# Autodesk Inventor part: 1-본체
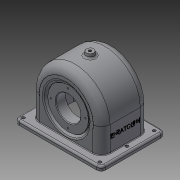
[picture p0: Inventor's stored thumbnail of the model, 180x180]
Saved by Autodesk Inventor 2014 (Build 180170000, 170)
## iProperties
Created: 2015-09
Part Number: 1-본체
Material: 일반
Document SubType Name: Modeling
Designer: Administrator
Density: 1 g/cm^3
Appearance: 기본값
Author: Administrator
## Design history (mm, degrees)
sketch "스케치1"
  geometry: L1 (57, 0)-(-57, 0); L2 (-57, 0)-(-57, -40); L3 (-57, -40)-(57, -40); L4 (57, -40)-(57, 0); L5 (70, -40)-(-70, -40); L6 (-70, -40)-(-70, -47); L7 (-70, -47)-(70, -47); L8 (70, -47)-(70, -40); A1 r 57 centre (0, 0) between (57, 0) and (40.608, -40); 6 further points
  constraints: 16 end point, 5 point on circle, 4 parallel, 4 point on line, 3 midpoint, 2 coincident, 2 horizontal, 2 perpendicular, 1 centre point
  dimensions: "d0" = 114 diameter of A1; "d1" = 7 distance of L5.end L6.end; "d2" = 47 distance between parallel lines of L1 L7; "d3" = 140 distance of L6.end L7.end
extrude "돌출1" new body sketch "스케치1" stored distance "d4" = 77; taper "d5" = 0 deg
extrude "돌출2" join sketch "스케치1" stored distance "d6" = 104; taper "d7" = 0 deg
fillet "모깎기1" dims "d12" = 14
feature "쉘1" dims "d13" = 7, "d14" = 5
sketch "스케치2"
  geometry: L1 (-38.5, 43.943)-(-38.5, 0); L2 (-38.5, 0)-(-19.5, 0); L3 (-19.5, 0)-(-19.5, 28); L4 (-19.5, 28)-(-38.5, 43.943); L5 (-38.5, 0)-(-38.5, 43) reference; L6 (24.5, 0)-(-24.5, 0) reference; L7 (-33.5, 33.22)-(-33.5, 5); L8 (-33.5, 5)-(-24.5, 5); L9 (-24.5, 5)-(-24.5, 25.668); L10 (-24.5, 25.668)-(-33.5, 33.22); L11 (-38.5, 37.416)-(-19.5, 21.473); 1 further point
  constraints: 18 end point, 3 point on line, 2 collinear, 2 parallel, 2 perpendicular, 1 midpoint, 1 vertical, 3 other
  dimensions: "d24" = 19 distance between parallel lines of L1 L3; "d25" = 50 deg angle of L3 L4; "d27" = 56 diameter of L3.end L2; "d28" = 5 distance between parallel lines of L4 L10
revolve "회전4" sketch "스케치2" stored, may be unused: angle "d29" = 90 deg
sketch "스케치10"
  geometry: L1 (113, -90.5)-(88.193, -90.5) reference; L2 (51.807, -90.5)-(27, -90.5) reference; L3 (30.253, -85.5)-(109.747, -85.5) reference; L4 (88.193, -90.5)-(51.807, -90.5); L5 (51.807, -90.5)-(51.807, -85.5); L6 (51.807, -85.5)-(88.193, -85.5); L7 (88.193, -85.5)-(88.193, -90.5); 1 further point
  constraints: 8 end point, 2 parallel, 1 horizontal, 1 perpendicular, 1 point on line
extrude "돌출6" join sketch "스케치10" stored distance "d94" = 10; taper "d95" = 0 deg
sketch "스케치4"
  geometry: L1 (-33.5, 39.747)-(-38.5, 43.943); L2 (-36.714, 35.917)-(-41.684, 40.087); L3 (-38.5, 43.943)-(-19.5, 28); L4 (-19.5, 28)-(-19.5, 20); L5 (-19.5, 20)-(-38.5, 20); L6 (-38.5, 20)-(-38.5, 43.943); L7 (-72.8, 0)-(72.8, 0) reference; L8 (-38.5, 37.416)-(-19.5, 21.473); L9 (-38.5, -40)-(-38.5, -9.054) reference; L10 (-33.5, 39.747)-(-38.47, 43.918) reference; 1 further point
  constraints: 14 end point, 3 collinear, 3 point on line, 2 perpendicular, 1 parallel, 1 vertical
  dimensions: "d30" = 5 distance between parallel lines of L1 L2; "d31" = 19 distance of L4.end L5.end; "d32" = 40 diameter of L5 L7; "d119" = 50 deg angle of L4 L3 (derived)
revolve "회전5" sketch "스케치4" stored, may be unused: angle "d34" = 90 deg
node "작업 평면2"
sketch "스케치5"
  geometry: C1 r 33 at (0, 0); 1 further point
  constraints: 1 centre point, 1 coincident
  dimensions: "d36" = 66 diameter of C1
extrude "돌출3" join sketch "스케치5" stored distance "d37" = 16; taper "d38" = 0 deg
sketch "스케치6"
  geometry: C1 r 31 at (0, 0); 1 further point
  constraints: 1 centre point, 1 coincident
  dimensions: "d39" = 62 diameter of C1
extrude "돌출4" join sketch "스케치6" distance "d40" = 10; taper "d41" = 0 deg
sketch "스케치13"
  geometry: C1 r 28 at (0, 0) reference; 1 further point
extrude "돌출7" cut sketch "스케치13" stored distance "d120" = 10; taper "d121" = 0 deg
hole "구멍1" diameter "d44" = 40; stored, may be unused: countersink angle "d48" = 90 deg, drill point angle "d50" = 118 deg; dims "d45" = 6, "d46" = 4, "d47" = 2, "d49" = 40, "d51" = 10, "d52" = 10
chamfer "모따기1" distance "d53" = 1; stored, may be unused: second distance "d54" = 2, angle "d55" = 45 deg
fillet "모깎기2" dims "d56" = 0.5
fillet "모깎기3" dims "d57" = 3
fillet "모깎기4" dims "d58" = 3
node "작업 평면4"
  node "작업 평면3"
sketch "스케치7"
  geometry: C1 r 6 at (0, 0); 1 further point
  constraints: 1 centre point, 1 coincident
  dimensions: "d60" = 12 diameter of C1
extrude "돌출5" join sketch "스케치7" stored distance "d61" = 10; taper "d62" = 10 deg
fillet "모깎기5" dims "d63" = 3
hole "구멍2" diameter "d66" = 4.459; stored, may be unused: countersink angle "d70" = 90 deg, drill point angle "d72" = 118 deg; dims "d64" = 10, "d65" = 10, "d67" = 15, "d68" = 4, "d69" = 2, "d71" = 40
fillet "모깎기6" dims "d73" = 7
sketch "스케치8"
  geometry: C1 r 2.5 at (0, 7); A1 r 7 centre (0, 7) between (-7, 7) and (0, 0) reference; 1 further point
  constraints: 1 centre point, 1 concentric
  dimensions: "d74" = 5 diameter of C1
hole "구멍3" sketch "스케치8" at (0, 7) diameter "d75" = 5; stored, may be unused: countersink angle "d79" = 90 deg, drill point angle "d81" = 118 deg; dims "d76" = 5, "d77" = 4, "d78" = 2, "d80" = 40
fillet "모깎기7" dims "d88" = 3
sketch "스케치9"
  geometry: L1 (12.171, 22.074)-(12.171, 26.926); L2 (12.171, 26.926)-(21.829, 26.926); L3 (21.829, 26.926)-(21.829, 22.074); L4 (21.829, 22.074)-(12.171, 22.074); L5 (0, 0)-(0, 49) reference; L6 (9.054, -14)-(40, -14) reference; L7 (47, -20.5)-(47, 69.5) reference; 4 further points
  constraints: 3 midpoint, 1 horizontal alignment, 1 vertical, 2 other
  dimensions: "d89" = 38.5 distance from line of L6 point (12.171, 24.5) (derived); "d90" = 30 distance from line of L7 point (17, 22.074)
feature "엠보싱1" sketch "스케치9" dims "d0" = 114, "d1" = 7, "d2" = 47, "d3" = 140, "d91" = 0.5, "d92" = 0
fillet "모깎기9" dims "d96" = 1
sketch "스케치11"
  geometry: L1 (0, 0)-(0, 28)
  constraints: 2 end point, 1 vertical
  dimensions: "d97" = 28 distance of L1.start L1.end
hole "구멍4" sketch "스케치11" at (0, 28) diameter "d98" = 2.459; stored, may be unused: countersink angle "d102" = 90 deg, drill point angle "d104" = 118 deg; dims "d99" = 7, "d100" = 4, "d101" = 2, "d103" = 9
sketch "스케치12"
  geometry: L1 (0, 0)-(0, -24)
  constraints: 2 end point, 1 vertical
  dimensions: "d108" = 24 distance of L1.start L1.end
hole "구멍5" sketch "스케치12" at (0, -24) diameter "d109" = 2.459; stored, may be unused: countersink angle "d113" = 90 deg, drill point angle "d115" = 118 deg; dims "d110" = 6, "d111" = 4, "d112" = 2, "d114" = 8
node "솔리드1"
pattern_linear "직사각형 패턴1" dims "d84" = 124, "d87" = 44
pattern_circular "원형 패턴1" dims angle "d106" = 360 deg
pattern_circular "원형 패턴2" dims angle "d117" = 360 deg
other parameters: "d35" = -16, "d59" = 6
